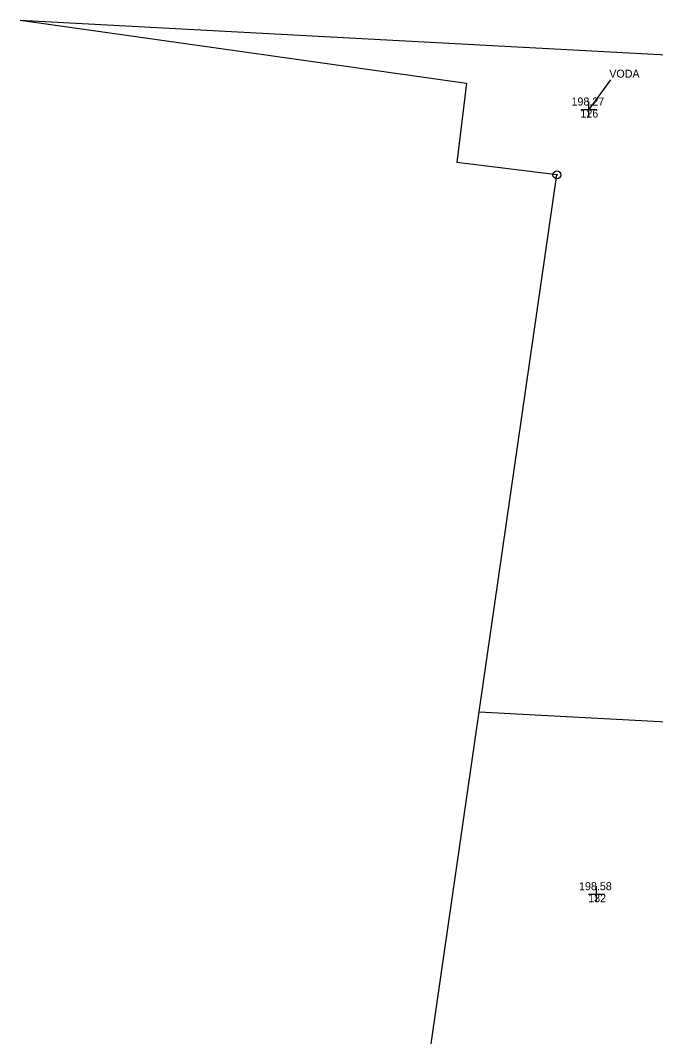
# Model space of a CAD drawing. Extents: x -706631 to -706106, y -1036183 to -1035074.
# Drawn here: x -706280 to -706240.3, y -1035676.6 to -1035613.2 of the extents above; entities that cross this region are included whole.
import ezdxf

# ---------------------------------------------------------------- set-up
doc = ezdxf.new("R2010")
doc.units = 0
for name, color, linetype in [('Hranice parcel', 7, 'Continuous'), ('křížky', 7, 'Continuous'), ('Stávající terén', 7, 'Continuous'), ('výšky', 7, 'Continuous'), ('Značky bodu BP', 7, 'Continuous'), ('čísla bodu', 7, 'Continuous')]:
    doc.layers.add(name, color=color, linetype=linetype)

msp = doc.modelspace()

# ---------------------------------------------------------------- linework, layer by layer
at = {"layer": 'Hranice parcel'}
for p, q in [((-706280.04, -1035613.17), (-706228.12, -1035615.93)), ((-706256.93, -1035694.84), (-706251.35, -1035656.36)), ((-706251.35, -1035656.36), (-706223.64, -1035657.84))]:
    msp.add_line(p, q, dxfattribs=at)
for points in [[(-706280.04, -1035613.17), (-706252.14, -1035617.09), (-706252.76, -1035622.04)], [(-706251.35, -1035656.36), (-706246.49, -1035622.82), (-706252.76, -1035622.04)]]:
    msp.add_lwpolyline(points, dxfattribs=at)
at = {"layer": 'křížky'}
for p, q in [((-706244.99, -1035618.74), (-706243.99, -1035618.74)), ((-706244.49, -1035619.24), (-706244.49, -1035618.24)), ((-706244.49, -1035618.74), (-706244.49, -1035618.74)), ((-706244.02, -1035668.25), (-706244.02, -1035667.25)), ((-706244.52, -1035667.75), (-706243.52, -1035667.75)), ((-706244.02, -1035667.75), (-706244.02, -1035667.75))]:
    msp.add_line(p, q, dxfattribs=at)
at = {"layer": 'Stávající terén'}
msp.add_line((-706243.152, -1035616.887), (-706244.49, -1035618.74), dxfattribs=at)
at = {"layer": 'Značky bodu BP'}
for radius in [0.25, 0.0152]:
    msp.add_circle((-706246.49, -1035622.82), radius, dxfattribs=at)
at = {"layer": 'čísla bodu'}
for p, q in [((-706244.99, -1035618.74), (-706243.99, -1035618.74)), ((-706244.49, -1035619.24), (-706244.49, -1035618.24)), ((-706244.49, -1035618.74), (-706244.49, -1035618.74)), ((-706244.02, -1035668.25), (-706244.02, -1035667.25)), ((-706244.52, -1035667.75), (-706243.52, -1035667.75)), ((-706244.02, -1035667.75), (-706244.02, -1035667.75))]:
    msp.add_line(p, q, dxfattribs=at)

# ---------------------------------------------------------------- texts
at = {"layer": 'Stávající terén'}
msp.add_text('VODA', height=0.5, dxfattribs=at).set_placement((-706243.22, -1035616.75))
at = {"layer": 'výšky'}
for s, p in [('198.27', (-706245.582, -1035618.49)), ('198.58', (-706245.112, -1035667.5))]:
    msp.add_text(s, height=0.5, dxfattribs=at).set_placement(p)
at = {"layer": 'čísla bodu'}
for s, p in [('126', (-706245.024, -1035619.24)), ('132', (-706244.54, -1035668.25))]:
    msp.add_text(s, height=0.5, dxfattribs=at).set_placement(p)

doc.saveas('drawing.dxf')
